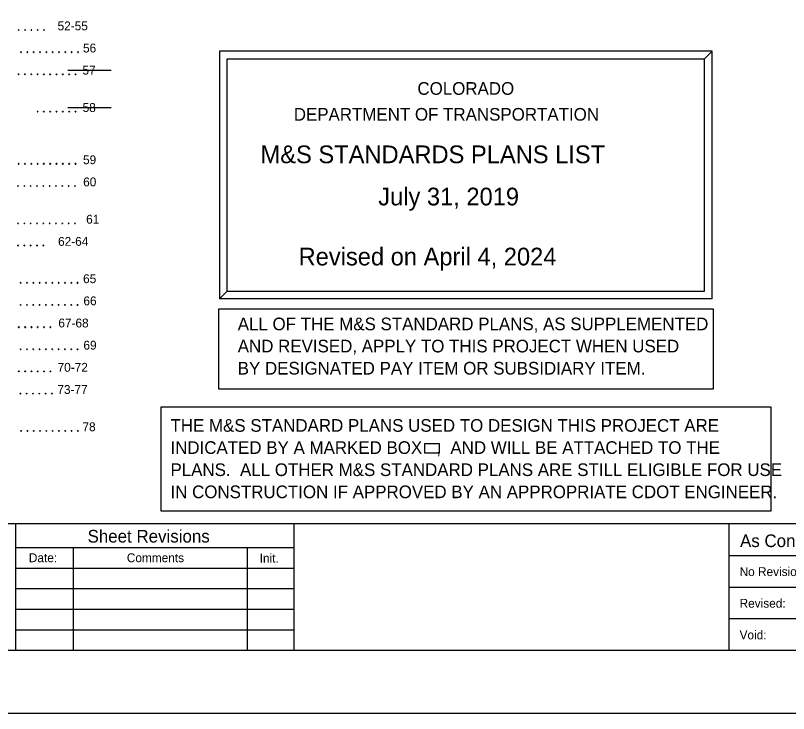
# Model space of a CAD drawing. Extents: x 0 to 1.42, y 0 to 0.92.
# Drawn here: x 0.432 to 0.942, y 0 to 0.46 of the extents above; entities that cross this region are included whole.
import ezdxf

# ---------------------------------------------------------------- set-up
doc = ezdxf.new("R2010")
doc.units = 0
for name, color, linetype in [('DRAFT_Text-Misc', 7, 'Continuous'), ('DRAFT_Text-Notes', 7, 'Continuous'), ('DRAFT_Text-Titles', 7, 'Continuous'), ('SHEET_Lines', 7, 'Continuous'), ('SHEET_Plot Boundary', 7, 'Continuous'), ('SHEET_Text-Border Info', 7, 'Continuous'), ('SHEET_Text-Titles', 7, 'Continuous')]:
    doc.layers.add(name, color=color, linetype=linetype)

msp = doc.modelspace()

# ---------------------------------------------------------------- linework, layer by layer
at = {"layer": 'DRAFT_Text-Notes'}
for centre in [(0.43439, 0.45026), (0.43856, 0.45026), (0.44272, 0.45026), (0.44689, 0.45026), (0.45106, 0.45026), (0.4359, 0.43567), (0.44006, 0.43567), (0.44423, 0.43567), (0.4484, 0.43567), (0.45256, 0.43567), (0.45673, 0.43567), (0.4609, 0.43567), (0.46506, 0.43567), (0.46923, 0.43567), (0.4734, 0.43567), (0.43429, 0.42108), (0.43845, 0.42108), (0.44262, 0.42108), (0.44679, 0.42108), (0.45095, 0.42108), (0.45512, 0.42108), (0.45929, 0.42108), (0.46345, 0.42108), (0.46762, 0.42108), (0.47179, 0.42108), (0.44679, 0.39648), (0.45095, 0.39648), (0.45512, 0.39648), (0.45929, 0.39648), (0.46345, 0.39648), (0.46762, 0.39648), (0.47179, 0.39648), (0.43429, 0.36209), (0.43845, 0.36209), (0.44262, 0.36209), (0.44679, 0.36209), (0.45095, 0.36209), (0.45512, 0.36209), (0.45929, 0.36209), (0.46345, 0.36209), (0.46762, 0.36209), (0.47179, 0.36209), (0.4339, 0.3475), (0.43807, 0.3475), (0.44224, 0.3475), (0.4464, 0.3475), (0.45057, 0.3475), (0.45474, 0.3475), (0.4589, 0.3475), (0.46307, 0.3475), (0.46724, 0.3475), (0.4714, 0.3475), (0.4339, 0.3229), (0.43807, 0.3229), (0.44224, 0.3229), (0.4464, 0.3229), (0.45057, 0.3229), (0.45474, 0.3229), (0.4589, 0.3229), (0.46307, 0.3229), (0.46724, 0.3229), (0.4714, 0.3229), (0.4339, 0.30831), (0.43807, 0.30831), (0.44224, 0.30831), (0.4464, 0.30831), (0.45057, 0.30831), (0.43564, 0.28372), (0.43981, 0.28372), (0.44398, 0.28372), (0.44814, 0.28372), (0.45231, 0.28372), (0.45648, 0.28372), (0.46064, 0.28372), (0.46481, 0.28372), (0.46898, 0.28372), (0.47314, 0.28372), (0.43564, 0.26913), (0.43981, 0.26913), (0.44398, 0.26913), (0.44814, 0.26913), (0.45231, 0.26913), (0.45648, 0.26913), (0.46064, 0.26913), (0.46481, 0.26913), (0.46898, 0.26913), (0.47314, 0.26913), (0.43441, 0.25454), (0.43858, 0.25454), (0.44275, 0.25454), (0.44691, 0.25454), (0.45108, 0.25454), (0.45525, 0.25454), (0.43564, 0.23994), (0.43981, 0.23994), (0.44398, 0.23994), (0.44814, 0.23994), (0.45231, 0.23994), (0.45648, 0.23994), (0.46064, 0.23994), (0.46481, 0.23994), (0.46898, 0.23994), (0.47314, 0.23994), (0.43441, 0.22535), (0.43858, 0.22535), (0.44275, 0.22535), (0.44691, 0.22535), (0.45108, 0.22535), (0.45525, 0.22535), (0.43544, 0.21076), (0.43961, 0.21076), (0.44377, 0.21076), (0.44794, 0.21076), (0.45211, 0.21076), (0.45627, 0.21076), (0.43589, 0.18617), (0.44006, 0.18617), (0.44423, 0.18617), (0.44839, 0.18617), (0.45256, 0.18617), (0.45673, 0.18617), (0.46089, 0.18617), (0.46506, 0.18617), (0.46923, 0.18617), (0.47339, 0.18617)]:
    msp.add_circle(centre, 0.000208, dxfattribs=at)
for centre, start, end in [((0.43439, 0.45026), 0, 180), ((0.43439, 0.45026), 180, 0), ((0.43856, 0.45026), 0, 180), ((0.43856, 0.45026), 180, 0), ((0.44272, 0.45026), 0, 180), ((0.44272, 0.45026), 180, 0), ((0.44689, 0.45026), 0, 180), ((0.44689, 0.45026), 180, 0), ((0.45106, 0.45026), 0, 180), ((0.45106, 0.45026), 180, 0), ((0.4359, 0.43567), 0, 180), ((0.4359, 0.43567), 180, 0), ((0.44006, 0.43567), 0, 180), ((0.44006, 0.43567), 180, 0), ((0.44423, 0.43567), 0, 180), ((0.44423, 0.43567), 180, 0), ((0.4484, 0.43567), 0, 180), ((0.4484, 0.43567), 180, 0), ((0.45256, 0.43567), 0, 180), ((0.45256, 0.43567), 180, 0), ((0.45673, 0.43567), 0, 180), ((0.45673, 0.43567), 180, 0), ((0.4609, 0.43567), 0, 180), ((0.4609, 0.43567), 180, 0), ((0.46506, 0.43567), 0, 180), ((0.46506, 0.43567), 180, 0), ((0.46923, 0.43567), 0, 180), ((0.46923, 0.43567), 180, 0), ((0.4734, 0.43567), 0, 180), ((0.4734, 0.43567), 180, 0), ((0.43429, 0.42108), 0, 180), ((0.43429, 0.42108), 180, 0), ((0.43845, 0.42108), 0, 180), ((0.43845, 0.42108), 180, 0), ((0.44262, 0.42108), 0, 180), ((0.44262, 0.42108), 180, 0), ((0.44679, 0.42108), 0, 180), ((0.44679, 0.42108), 180, 0), ((0.45095, 0.42108), 0, 180), ((0.45095, 0.42108), 180, 0), ((0.45512, 0.42108), 0, 180), ((0.45512, 0.42108), 180, 0), ((0.45929, 0.42108), 0, 180), ((0.45929, 0.42108), 180, 0), ((0.46345, 0.42108), 0, 180), ((0.46345, 0.42108), 180, 0), ((0.46762, 0.42108), 0, 180), ((0.46762, 0.42108), 180, 0), ((0.47179, 0.42108), 0, 180), ((0.47179, 0.42108), 180, 0), ((0.44679, 0.39648), 0, 180), ((0.44679, 0.39648), 180, 0), ((0.45095, 0.39648), 0, 180), ((0.45095, 0.39648), 180, 0), ((0.45512, 0.39648), 0, 180), ((0.45512, 0.39648), 180, 0), ((0.45929, 0.39648), 0, 180), ((0.45929, 0.39648), 180, 0), ((0.46345, 0.39648), 0, 180), ((0.46345, 0.39648), 180, 0), ((0.46762, 0.39648), 0, 180), ((0.46762, 0.39648), 180, 0), ((0.47179, 0.39648), 0, 180), ((0.47179, 0.39648), 180, 0), ((0.43429, 0.36209), 0, 180), ((0.43429, 0.36209), 180, 0), ((0.43845, 0.36209), 0, 180), ((0.43845, 0.36209), 180, 0), ((0.44262, 0.36209), 0, 180), ((0.44262, 0.36209), 180, 0), ((0.44679, 0.36209), 0, 180), ((0.44679, 0.36209), 180, 0), ((0.45095, 0.36209), 0, 180), ((0.45095, 0.36209), 180, 0), ((0.45512, 0.36209), 0, 180), ((0.45512, 0.36209), 180, 0), ((0.45929, 0.36209), 0, 180), ((0.45929, 0.36209), 180, 0), ((0.46345, 0.36209), 0, 180), ((0.46345, 0.36209), 180, 0), ((0.46762, 0.36209), 0, 180), ((0.46762, 0.36209), 180, 0), ((0.47179, 0.36209), 0, 180), ((0.47179, 0.36209), 180, 0), ((0.4339, 0.3475), 0, 180), ((0.4339, 0.3475), 180, 0), ((0.43807, 0.3475), 0, 180), ((0.43807, 0.3475), 180, 0), ((0.44224, 0.3475), 0, 180), ((0.44224, 0.3475), 180, 0), ((0.4464, 0.3475), 0, 180), ((0.4464, 0.3475), 180, 0), ((0.45057, 0.3475), 0, 180), ((0.45057, 0.3475), 180, 0), ((0.45474, 0.3475), 0, 180), ((0.45474, 0.3475), 180, 0), ((0.4589, 0.3475), 0, 180), ((0.4589, 0.3475), 180, 0), ((0.46307, 0.3475), 0, 180), ((0.46307, 0.3475), 180, 0), ((0.46724, 0.3475), 0, 180), ((0.46724, 0.3475), 180, 0), ((0.4714, 0.3475), 0, 180), ((0.4714, 0.3475), 180, 0), ((0.4339, 0.3229), 0, 180), ((0.4339, 0.3229), 180, 0), ((0.43807, 0.3229), 0, 180), ((0.43807, 0.3229), 180, 0), ((0.44224, 0.3229), 0, 180), ((0.44224, 0.3229), 180, 0), ((0.4464, 0.3229), 0, 180), ((0.4464, 0.3229), 180, 0), ((0.45057, 0.3229), 0, 180), ((0.45057, 0.3229), 180, 0), ((0.45474, 0.3229), 0, 180), ((0.45474, 0.3229), 180, 0), ((0.4589, 0.3229), 0, 180), ((0.4589, 0.3229), 180, 0), ((0.46307, 0.3229), 0, 180), ((0.46307, 0.3229), 180, 0), ((0.46724, 0.3229), 0, 180), ((0.46724, 0.3229), 180, 0), ((0.4714, 0.3229), 0, 180), ((0.4714, 0.3229), 180, 0), ((0.4339, 0.30831), 0, 180), ((0.4339, 0.30831), 180, 0), ((0.43807, 0.30831), 0, 180), ((0.43807, 0.30831), 180, 0), ((0.44224, 0.30831), 0, 180), ((0.44224, 0.30831), 180, 0), ((0.4464, 0.30831), 0, 180), ((0.4464, 0.30831), 180, 0), ((0.45057, 0.30831), 0, 180), ((0.45057, 0.30831), 180, 0), ((0.43564, 0.28372), 0, 180), ((0.43564, 0.28372), 180, 0), ((0.43981, 0.28372), 0, 180), ((0.43981, 0.28372), 180, 0), ((0.44398, 0.28372), 0, 180), ((0.44398, 0.28372), 180, 0), ((0.44814, 0.28372), 0, 180), ((0.44814, 0.28372), 180, 0), ((0.45231, 0.28372), 0, 180), ((0.45231, 0.28372), 180, 0), ((0.45648, 0.28372), 0, 180), ((0.45648, 0.28372), 180, 0), ((0.46064, 0.28372), 0, 180), ((0.46064, 0.28372), 180, 0), ((0.46481, 0.28372), 0, 180), ((0.46481, 0.28372), 180, 0), ((0.46898, 0.28372), 0, 180), ((0.46898, 0.28372), 180, 0), ((0.47314, 0.28372), 0, 180), ((0.47314, 0.28372), 180, 0), ((0.43564, 0.26913), 0, 180), ((0.43564, 0.26913), 180, 0), ((0.43981, 0.26913), 0, 180), ((0.43981, 0.26913), 180, 0), ((0.44398, 0.26913), 0, 180), ((0.44398, 0.26913), 180, 0), ((0.44814, 0.26913), 0, 180), ((0.44814, 0.26913), 180, 0), ((0.45231, 0.26913), 0, 180), ((0.45231, 0.26913), 180, 0), ((0.45648, 0.26913), 0, 180), ((0.45648, 0.26913), 180, 0), ((0.46064, 0.26913), 0, 180), ((0.46064, 0.26913), 180, 0), ((0.46481, 0.26913), 0, 180), ((0.46481, 0.26913), 180, 0), ((0.46898, 0.26913), 0, 180), ((0.46898, 0.26913), 180, 0), ((0.47314, 0.26913), 0, 180), ((0.47314, 0.26913), 180, 0), ((0.43441, 0.25454), 0, 180), ((0.43441, 0.25454), 180, 0), ((0.43858, 0.25454), 0, 180), ((0.43858, 0.25454), 180, 0), ((0.44275, 0.25454), 0, 180), ((0.44275, 0.25454), 180, 0), ((0.44691, 0.25454), 0, 180), ((0.44691, 0.25454), 180, 0), ((0.45108, 0.25454), 0, 180), ((0.45108, 0.25454), 180, 0), ((0.45525, 0.25454), 0, 180), ((0.45525, 0.25454), 180, 0), ((0.43564, 0.23994), 0, 180), ((0.43564, 0.23994), 180, 0), ((0.43981, 0.23994), 0, 180), ((0.43981, 0.23994), 180, 0), ((0.44398, 0.23994), 0, 180), ((0.44398, 0.23994), 180, 0), ((0.44814, 0.23994), 0, 180), ((0.44814, 0.23994), 180, 0), ((0.45231, 0.23994), 0, 180), ((0.45231, 0.23994), 180, 0), ((0.45648, 0.23994), 0, 180), ((0.45648, 0.23994), 180, 0), ((0.46064, 0.23994), 0, 180), ((0.46064, 0.23994), 180, 0), ((0.46481, 0.23994), 0, 180), ((0.46481, 0.23994), 180, 0), ((0.46898, 0.23994), 0, 180), ((0.46898, 0.23994), 180, 0), ((0.47314, 0.23994), 0, 180), ((0.47314, 0.23994), 180, 0), ((0.43441, 0.22535), 0, 180), ((0.43441, 0.22535), 180, 0), ((0.43858, 0.22535), 0, 180), ((0.43858, 0.22535), 180, 0), ((0.44275, 0.22535), 0, 180), ((0.44275, 0.22535), 180, 0), ((0.44691, 0.22535), 0, 180), ((0.44691, 0.22535), 180, 0), ((0.45108, 0.22535), 0, 180), ((0.45108, 0.22535), 180, 0), ((0.45525, 0.22535), 0, 180), ((0.45525, 0.22535), 180, 0), ((0.43544, 0.21076), 0, 180), ((0.43544, 0.21076), 180, 0), ((0.43961, 0.21076), 0, 180), ((0.43961, 0.21076), 180, 0), ((0.44377, 0.21076), 0, 180), ((0.44377, 0.21076), 180, 0), ((0.44794, 0.21076), 0, 180), ((0.44794, 0.21076), 180, 0), ((0.45211, 0.21076), 0, 180), ((0.45211, 0.21076), 180, 0), ((0.45627, 0.21076), 0, 180), ((0.45627, 0.21076), 180, 0), ((0.43589, 0.18617), 0, 180), ((0.43589, 0.18617), 180, 0), ((0.44006, 0.18617), 0, 180), ((0.44006, 0.18617), 180, 0), ((0.44423, 0.18617), 0, 180), ((0.44423, 0.18617), 180, 0), ((0.44839, 0.18617), 0, 180), ((0.44839, 0.18617), 180, 0), ((0.45256, 0.18617), 0, 180), ((0.45256, 0.18617), 180, 0), ((0.45673, 0.18617), 0, 180), ((0.45673, 0.18617), 180, 0), ((0.46089, 0.18617), 0, 180), ((0.46089, 0.18617), 180, 0), ((0.46506, 0.18617), 0, 180), ((0.46506, 0.18617), 180, 0), ((0.46923, 0.18617), 0, 180), ((0.46923, 0.18617), 180, 0), ((0.47339, 0.18617), 0, 180), ((0.47339, 0.18617), 180, 0)]:
    msp.add_arc(centre, 0.000208, start, end, dxfattribs=at)
at = {"layer": 'DRAFT_Text-Titles'}
for p, q in [((0.46677, 0.4237), (0.49535, 0.4237)), ((0.46677, 0.39911), (0.49535, 0.39911))]:
    msp.add_line(p, q, dxfattribs=at)
at = {"layer": 'SHEET_Lines'}
for p, q in [((0.89151, 0.43623), (0.56682, 0.43623)), ((0.56682, 0.43623), (0.56682, 0.27313)), ((0.88651, 0.43122), (0.89151, 0.43623)), ((0.57183, 0.27813), (0.57183, 0.43122)), ((0.57183, 0.43122), (0.88651, 0.43122)), ((0.88651, 0.27813), (0.88651, 0.43122)), ((0.56682, 0.27313), (0.57183, 0.27813)), ((0.57183, 0.27813), (0.88651, 0.27813)), ((0.89151, 0.27313), (0.56682, 0.27313)), ((0.43238, 0.04167), (0.43238, 0.125)), ((0.61597, 0.04167), (0.61597, 0.125)), ((0.90278, 0.04167), (0.90278, 0.125)), ((0.43238, 0.10938), (0.61597, 0.10938)), ((0.47057, 0.04167), (0.47057, 0.10938)), ((0.58516, 0.04167), (0.58516, 0.10938)), ((0.90278, 0.10417), (1.01389, 0.10417)), ((0.43238, 0.09583), (0.61597, 0.09583)), ((0.43238, 0.08229), (0.61597, 0.08229)), ((0.90278, 0.08333), (1.375, 0.08333)), ((0.43238, 0.06875), (0.61597, 0.06875)), ((0.90278, 0.0625), (1.01389, 0.0625)), ((0.43238, 0.05521), (0.61597, 0.05521)), ((0.08333, 0.04167), (1.375, 0.04167))]:
    msp.add_line(p, q, dxfattribs=at)
msp.add_lwpolyline([(0.08333, 0.875), (1.375, 0.875), (1.375, 0.125), (0.08333, 0.125)], close=True, dxfattribs=at)
for points in [[(0.89151, 0.27313), (0.89151, 0.43623)], [(0.56605, 0.21393), (0.89229, 0.21393), (0.89229, 0.26642), (0.56605, 0.26642), (0.56605, 0.21393)], [(0.52804, 0.13357), (0.9303, 0.13357), (0.9303, 0.20174), (0.52804, 0.20174), (0.52804, 0.13357)], [(0.70178, 0.17167), (0.71175, 0.17167), (0.71175, 0.17756), (0.70178, 0.17756), (0.70178, 0.17167)]]:
    msp.add_lwpolyline(points, dxfattribs=at)
at = {"layer": 'SHEET_Plot Boundary'}
msp.add_lwpolyline([(0, 0.91667), (1.41667, 0.91667), (1.41667, 0), (0, 0)], close=True, dxfattribs=at)

# ---------------------------------------------------------------- texts
at = {"layer": 'DRAFT_Text-Misc'}
for s, p in [('ALL OF THE M&S STANDARD PLANS, AS SUPPLEMENTED', (0.57874, 0.25247)), ('AND REVISED, APPLY TO THIS PROJECT WHEN USED', (0.57874, 0.23789)), ('BY DESIGNATED PAY ITEM OR SUBSIDIARY ITEM.', (0.57874, 0.2233)), ('THE M&S STANDARD PLANS USED TO DESIGN THIS PROJECT ARE', (0.5344, 0.18561)), ('INDICATED BY A MARKED BOX   ,  AND WILL BE ATTACHED TO THE', (0.5344, 0.17103)), ('PLANS.  ALL OTHER M&S STANDARD PLANS ARE STILL ELIGIBLE FOR USE', (0.5344, 0.15645)), ('IN CONSTRUCTION IF APPROVED BY AN APPROPRIATE CDOT ENGINEER.', (0.5344, 0.14186))]:
    msp.add_text(s, height=0.0083333, dxfattribs=at).set_placement(p)
at = {"layer": 'DRAFT_Text-Notes'}
for s, p in [('52-55', (0.45998, 0.45005)), ('56', (0.47674, 0.43546)), ('57', (0.47638, 0.42087)), ('58', (0.47647, 0.39627)), ('59', (0.47674, 0.36188)), ('60', (0.47684, 0.34729)), ('61', (0.47881, 0.3227)), ('62-64', (0.46031, 0.3081)), ('65', (0.47679, 0.28351)), ('66', (0.47702, 0.26892)), ('67-68', (0.46049, 0.25433)), ('69', (0.47702, 0.23973)), ('70-72', (0.45999, 0.22514)), ('73-77', (0.45985, 0.21055)), ('78', (0.47638, 0.18596))]:
    msp.add_text(s, height=0.005833, dxfattribs=at).set_placement(p)
at = {"layer": 'DRAFT_Text-Titles'}
for s, height, p in [('COLORADO', 0.008333, (0.69719, 0.40759)), ('DEPARTMENT OF TRANSPORTATION', 0.0083333, (0.61568, 0.39055)), ('M&S STANDARDS PLANS LIST', 0.0116667, (0.59377, 0.36253)), ('July 31, 2019', 0.0116667, (0.67136, 0.33472)), ('Revised on April 4, 2024', 0.0116667, (0.61885, 0.29518))]:
    msp.add_text(s, height=height, dxfattribs=at).set_placement(p)
at = {"layer": 'SHEET_Text-Border Info'}
for s, height, p in [('Date:', 0.005833, (0.44104, 0.09969)), ('Comments', 0.005833, (0.50563, 0.09969)), ('Init.', 0.005833, (0.59322, 0.09941)), ('No Revisions:', 0.0058333, (0.90955, 0.09056)), ('Revised:', 0.005833, (0.90955, 0.06972)), ('Void:', 0.005833, (0.90955, 0.04889))]:
    msp.add_text(s, height=height, dxfattribs=at).set_placement(p)
at = {"layer": 'SHEET_Text-Titles'}
for s, p in [('Sheet Revisions', (0.47975, 0.11263)), ('As Constructed', (0.90984, 0.10964))]:
    msp.add_text(s, height=0.0083333, dxfattribs=at).set_placement(p)

doc.saveas('drawing.dxf')
